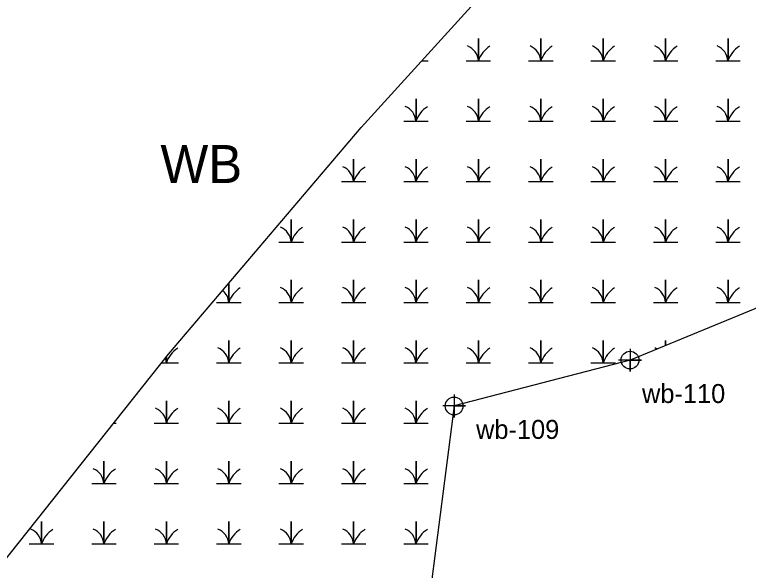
# Model space of a CAD drawing. Extents: x 2379288 to 2381905, y 330670 to 333511.
# Drawn here: x 2380290.9 to 2380484.3, y 332529.1 to 332675.5 of the extents above; entities that cross this region are included whole.
import ezdxf

# ---------------------------------------------------------------- set-up
doc = ezdxf.new("R2010")
doc.units = 0
for name, color, linetype in [('Default', 7, 'Continuous'), ('Exist Environmental Wetland Boundary', 7, 'Continuous'), ('Exist Environmental Wetland Boundary Cogo Number', 7, 'Continuous'), ('Exist Environmental Wetland Boundary Cogo Point CELL', 7, 'Continuous'), ('Exist Environmental Wetland Boundary Text', 7, 'Continuous'), ('Exist Hydro Swamp or Marsh', 7, 'Continuous')]:
    doc.layers.add(name, color=color, linetype=linetype)

msp = doc.modelspace()

# ---------------------------------------------------------------- linework, layer by layer
at = {"layer": 'Default'}
msp.add_lwpolyline([(2379288.07, 330873.37), (2380109.3, 332268.58), (2380147.86, 332331.82), (2380190.73, 332397.51), (2380235.65, 332461.81), (2380282.57, 332524.66), (2380331.46, 332586), (2380382.25, 332645.77), (2380434.91, 332703.9), (2380489.37, 332760.35), (2380545.59, 332815.05), (2380603.5, 332867.95), (2380663.06, 332918.99), (2380724.19, 332968.13), (2380786.85, 333015.32), (2380850.96, 333060.51), (2380916.47, 333103.65)], dxfattribs=at)
at = {"layer": 'Exist Environmental Wetland Boundary'}
msp.add_lwpolyline([(2380626.94, 332703.59), (2380578.61, 332658.53), (2380538.32, 332619.14), (2380494.95, 332601.64), (2380453.1, 332584.48), (2380406.72, 332572.38), (2380400.16, 332521.26), (2380412.11, 332496.92), (2380413.59, 332462.54), (2380386.06, 332425.71), (2380352.83, 332397.02), (2380315.67, 332385.64), (2380290.84, 332358.39), (2380295.85, 332340.3), (2380332.51, 332311.36), (2380326.97, 332300.58), (2380311.82, 332307.72), (2380244.82, 332322.56), (2380185.2, 332357.15), (2380173.71, 332371.44)], dxfattribs=at)
at = {"layer": 'Exist Environmental Wetland Boundary Cogo Point CELL'}
for points in [[(2380453.1, 332587.48), (2380453.1, 332581.48), (2380453.1, 332584.48), (2380456.1, 332584.48), (2380450.1, 332584.48)], [(2380406.72, 332575.38), (2380406.72, 332569.38), (2380406.72, 332572.38), (2380409.72, 332572.38), (2380403.72, 332572.38)]]:
    msp.add_lwpolyline(points, dxfattribs=at)
for centre in [(2380453.1, 332584.48), (2380406.72, 332572.38)]:
    msp.add_circle(centre, 2.34, dxfattribs=at)
at = {"layer": 'Exist Hydro Swamp or Marsh'}
for p, q in [((2380398.18, 332663.35), (2380399.9, 332663.35)), ((2380316.99, 332567.85), (2380317.65, 332567.85))]:
    msp.add_line(p, q, dxfattribs=at)
for points in [[(2380409.9, 332663.35), (2380413.13, 332663.35), (2380413.13, 332669.27), (2380413.13, 332663.35), (2380416.35, 332663.35)], [(2380426.35, 332663.35), (2380429.58, 332663.35), (2380429.58, 332669.27), (2380429.58, 332663.35), (2380432.81, 332663.35)], [(2380442.81, 332663.35), (2380446.03, 332663.35), (2380446.03, 332669.27), (2380446.03, 332663.35), (2380449.26, 332663.35)], [(2380459.26, 332663.35), (2380462.48, 332663.35), (2380462.48, 332669.27), (2380462.48, 332663.35), (2380465.71, 332663.35)], [(2380475.71, 332663.35), (2380478.93, 332663.35), (2380478.93, 332669.27), (2380478.93, 332663.35), (2380482.16, 332663.35)], [(2380393.45, 332647.43), (2380396.68, 332647.43), (2380396.68, 332653.35), (2380396.68, 332647.43), (2380399.9, 332647.43)], [(2380409.9, 332647.43), (2380413.13, 332647.43), (2380413.13, 332653.35), (2380413.13, 332647.43), (2380416.35, 332647.43)], [(2380426.35, 332647.43), (2380429.58, 332647.43), (2380429.58, 332653.35), (2380429.58, 332647.43), (2380432.81, 332647.43)], [(2380442.81, 332647.43), (2380446.03, 332647.43), (2380446.03, 332653.35), (2380446.03, 332647.43), (2380449.26, 332647.43)], [(2380459.26, 332647.43), (2380462.48, 332647.43), (2380462.48, 332653.35), (2380462.48, 332647.43), (2380465.71, 332647.43)], [(2380475.71, 332647.43), (2380478.93, 332647.43), (2380478.93, 332653.35), (2380478.93, 332647.43), (2380482.16, 332647.43)], [(2380377, 332631.52), (2380380.23, 332631.52), (2380380.23, 332637.43), (2380380.23, 332631.52), (2380383.45, 332631.52)], [(2380393.45, 332631.52), (2380396.68, 332631.52), (2380396.68, 332637.43), (2380396.68, 332631.52), (2380399.9, 332631.52)], [(2380409.9, 332631.52), (2380413.13, 332631.52), (2380413.13, 332637.43), (2380413.13, 332631.52), (2380416.35, 332631.52)], [(2380426.35, 332631.52), (2380429.58, 332631.52), (2380429.58, 332637.43), (2380429.58, 332631.52), (2380432.81, 332631.52)], [(2380442.81, 332631.52), (2380446.03, 332631.52), (2380446.03, 332637.43), (2380446.03, 332631.52), (2380449.26, 332631.52)], [(2380459.26, 332631.52), (2380462.48, 332631.52), (2380462.48, 332637.43), (2380462.48, 332631.52), (2380465.71, 332631.52)], [(2380475.71, 332631.52), (2380478.93, 332631.52), (2380478.93, 332637.43), (2380478.93, 332631.52), (2380482.16, 332631.52)], [(2380360.55, 332615.6), (2380363.78, 332615.6), (2380363.78, 332621.52), (2380363.78, 332615.6), (2380367, 332615.6)], [(2380377, 332615.6), (2380380.23, 332615.6), (2380380.23, 332621.52), (2380380.23, 332615.6), (2380383.45, 332615.6)], [(2380393.45, 332615.6), (2380396.68, 332615.6), (2380396.68, 332621.52), (2380396.68, 332615.6), (2380399.9, 332615.6)], [(2380409.9, 332615.6), (2380413.13, 332615.6), (2380413.13, 332621.52), (2380413.13, 332615.6), (2380416.35, 332615.6)], [(2380426.35, 332615.6), (2380429.58, 332615.6), (2380429.58, 332621.52), (2380429.58, 332615.6), (2380432.81, 332615.6)], [(2380442.81, 332615.6), (2380446.03, 332615.6), (2380446.03, 332621.52), (2380446.03, 332615.6), (2380449.26, 332615.6)], [(2380459.26, 332615.6), (2380462.48, 332615.6), (2380462.48, 332621.52), (2380462.48, 332615.6), (2380465.71, 332615.6)], [(2380475.71, 332615.6), (2380478.93, 332615.6), (2380478.93, 332621.52), (2380478.93, 332615.6), (2380482.16, 332615.6)], [(2380360.55, 332599.68), (2380363.78, 332599.68), (2380363.78, 332605.6), (2380363.78, 332599.68), (2380367, 332599.68)], [(2380377, 332599.68), (2380380.23, 332599.68), (2380380.23, 332605.6), (2380380.23, 332599.68), (2380383.45, 332599.68)], [(2380393.45, 332599.68), (2380396.68, 332599.68), (2380396.68, 332605.6), (2380396.68, 332599.68), (2380399.9, 332599.68)], [(2380409.9, 332599.68), (2380413.13, 332599.68), (2380413.13, 332605.6), (2380413.13, 332599.68), (2380416.35, 332599.68)], [(2380426.35, 332599.68), (2380429.58, 332599.68), (2380429.58, 332605.6), (2380429.58, 332599.68), (2380432.81, 332599.68)], [(2380442.81, 332599.68), (2380446.03, 332599.68), (2380446.03, 332605.6), (2380446.03, 332599.68), (2380449.26, 332599.68)], [(2380459.26, 332599.68), (2380462.48, 332599.68), (2380462.48, 332605.6), (2380462.48, 332599.68), (2380465.71, 332599.68)], [(2380475.71, 332599.68), (2380478.93, 332599.68), (2380478.93, 332605.6), (2380478.93, 332599.68), (2380482.16, 332599.68)], [(2380344.1, 332599.68), (2380347.32, 332599.68), (2380347.32, 332604.54)], [(2380347.32, 332604.54), (2380347.32, 332599.68), (2380350.55, 332599.68)], [(2380344.1, 332583.76), (2380347.32, 332583.76), (2380347.32, 332589.68), (2380347.32, 332583.76), (2380350.55, 332583.76)], [(2380360.55, 332583.76), (2380363.78, 332583.76), (2380363.78, 332589.68), (2380363.78, 332583.76), (2380367, 332583.76)], [(2380377, 332583.76), (2380380.23, 332583.76), (2380380.23, 332589.68), (2380380.23, 332583.76), (2380383.45, 332583.76)], [(2380393.45, 332583.76), (2380396.68, 332583.76), (2380396.68, 332589.68), (2380396.68, 332583.76), (2380399.9, 332583.76)], [(2380409.9, 332583.76), (2380413.13, 332583.76), (2380413.13, 332589.68), (2380413.13, 332583.76), (2380416.35, 332583.76)], [(2380426.35, 332583.76), (2380429.58, 332583.76), (2380429.58, 332589.68), (2380429.58, 332583.76), (2380432.81, 332583.76)], [(2380442.81, 332583.76), (2380446.03, 332583.76), (2380446.03, 332589.68), (2380446.03, 332583.76), (2380449.26, 332583.76)], [(2380462.48, 332588.33), (2380462.48, 332589.68), (2380462.48, 332588.33)], [(2380329.67, 332583.76), (2380330.87, 332583.76), (2380330.87, 332585.27)], [(2380330.87, 332585.27), (2380330.87, 332583.76), (2380334.1, 332583.76)], [(2380327.65, 332567.85), (2380330.87, 332567.85), (2380330.87, 332573.76), (2380330.87, 332567.85), (2380334.1, 332567.85)], [(2380344.1, 332567.85), (2380347.32, 332567.85), (2380347.32, 332573.76), (2380347.32, 332567.85), (2380350.55, 332567.85)], [(2380360.55, 332567.85), (2380363.78, 332567.85), (2380363.78, 332573.76), (2380363.78, 332567.85), (2380367, 332567.85)], [(2380377, 332567.85), (2380380.23, 332567.85), (2380380.23, 332573.76), (2380380.23, 332567.85), (2380383.45, 332567.85)], [(2380393.45, 332567.85), (2380396.68, 332567.85), (2380396.68, 332573.76), (2380396.68, 332567.85), (2380399.9, 332567.85)], [(2380311.2, 332551.93), (2380314.42, 332551.93), (2380314.42, 332557.85), (2380314.42, 332551.93), (2380317.65, 332551.93)], [(2380327.65, 332551.93), (2380330.87, 332551.93), (2380330.87, 332557.85), (2380330.87, 332551.93), (2380334.1, 332551.93)], [(2380344.1, 332551.93), (2380347.32, 332551.93), (2380347.32, 332557.85), (2380347.32, 332551.93), (2380350.55, 332551.93)], [(2380360.55, 332551.93), (2380363.78, 332551.93), (2380363.78, 332557.85), (2380363.78, 332551.93), (2380367, 332551.93)], [(2380377, 332551.93), (2380380.23, 332551.93), (2380380.23, 332557.85), (2380380.23, 332551.93), (2380383.45, 332551.93)], [(2380393.45, 332551.93), (2380396.68, 332551.93), (2380396.68, 332557.85), (2380396.68, 332551.93), (2380399.9, 332551.93)], [(2380294.74, 332536.01), (2380297.97, 332536.01), (2380297.97, 332541.93), (2380297.97, 332536.01), (2380301.2, 332536.01)], [(2380311.2, 332536.01), (2380314.42, 332536.01), (2380314.42, 332541.93), (2380314.42, 332536.01), (2380317.65, 332536.01)], [(2380327.65, 332536.01), (2380330.87, 332536.01), (2380330.87, 332541.93), (2380330.87, 332536.01), (2380334.1, 332536.01)], [(2380344.1, 332536.01), (2380347.32, 332536.01), (2380347.32, 332541.93), (2380347.32, 332536.01), (2380350.55, 332536.01)], [(2380360.55, 332536.01), (2380363.78, 332536.01), (2380363.78, 332541.93), (2380363.78, 332536.01), (2380367, 332536.01)], [(2380377, 332536.01), (2380380.23, 332536.01), (2380380.23, 332541.93), (2380380.23, 332536.01), (2380383.45, 332536.01)], [(2380393.45, 332536.01), (2380396.68, 332536.01), (2380396.68, 332541.93), (2380396.68, 332536.01), (2380399.9, 332536.01)]]:
    msp.add_lwpolyline(points, dxfattribs=at)
for centre, radius, start, end in [((2380408.53, 332663.02), 4.61, 4.1403, 67.535), ((2380419.97, 332661.08), 7.21, 122.1274, 161.6222), ((2380424.98, 332663.02), 4.61, 4.1403, 67.535), ((2380436.42, 332661.08), 7.21, 122.1274, 161.6222), ((2380441.43, 332663.02), 4.61, 4.1403, 67.535), ((2380452.87, 332661.08), 7.21, 122.1274, 161.6222), ((2380457.88, 332663.02), 4.61, 4.1403, 67.535), ((2380469.32, 332661.08), 7.21, 122.1274, 161.6222), ((2380474.33, 332663.02), 4.61, 4.1403, 67.535), ((2380485.77, 332661.08), 7.21, 122.1274, 161.6222), ((2380392.08, 332647.1), 4.61, 4.1403, 67.535), ((2380403.52, 332645.16), 7.21, 122.1274, 161.6222), ((2380408.53, 332647.1), 4.61, 4.1403, 67.535), ((2380419.97, 332645.16), 7.21, 122.1274, 161.6222), ((2380424.98, 332647.1), 4.61, 4.1403, 67.535), ((2380436.42, 332645.16), 7.21, 122.1274, 161.6222), ((2380441.43, 332647.1), 4.61, 4.1403, 67.535), ((2380452.87, 332645.16), 7.21, 122.1274, 161.6222), ((2380457.88, 332647.1), 4.61, 4.1403, 67.535), ((2380469.32, 332645.16), 7.21, 122.1274, 161.6222), ((2380474.33, 332647.1), 4.61, 4.1403, 67.535), ((2380485.77, 332645.16), 7.21, 122.1274, 161.6222), ((2380375.63, 332631.18), 4.61, 4.1403, 67.535), ((2380387.07, 332629.24), 7.21, 122.1274, 161.6222), ((2380392.08, 332631.18), 4.61, 4.1403, 67.535), ((2380403.52, 332629.24), 7.21, 122.1274, 161.6222), ((2380408.53, 332631.18), 4.61, 4.1403, 67.535), ((2380419.97, 332629.24), 7.21, 122.1274, 161.6222), ((2380424.98, 332631.18), 4.61, 4.1403, 67.535), ((2380436.42, 332629.24), 7.21, 122.1274, 161.6222), ((2380441.43, 332631.18), 4.61, 4.1403, 67.535), ((2380452.87, 332629.24), 7.21, 122.1274, 161.6222), ((2380457.88, 332631.18), 4.61, 4.1403, 67.535), ((2380469.32, 332629.24), 7.21, 122.1274, 161.6222), ((2380474.33, 332631.18), 4.61, 4.1403, 67.535), ((2380485.77, 332629.24), 7.21, 122.1274, 161.6222), ((2380359.18, 332615.27), 4.61, 4.1403, 67.535), ((2380370.62, 332613.33), 7.21, 122.1274, 161.6222), ((2380375.63, 332615.27), 4.61, 4.1403, 67.535), ((2380387.07, 332613.33), 7.21, 122.1274, 161.6222), ((2380392.08, 332615.27), 4.61, 4.1403, 67.535), ((2380403.52, 332613.33), 7.21, 122.1274, 161.6222), ((2380408.53, 332615.27), 4.61, 4.1403, 67.535), ((2380419.97, 332613.33), 7.21, 122.1274, 161.6222), ((2380424.98, 332615.27), 4.61, 4.1403, 67.535), ((2380436.42, 332613.33), 7.21, 122.1274, 161.6222), ((2380441.43, 332615.27), 4.61, 4.1403, 67.535), ((2380452.87, 332613.33), 7.21, 122.1274, 161.6222), ((2380457.88, 332615.27), 4.61, 4.1403, 67.535), ((2380469.32, 332613.33), 7.21, 122.1274, 161.6222), ((2380474.33, 332615.27), 4.61, 4.1403, 67.535), ((2380485.77, 332613.33), 7.21, 122.1274, 161.6222), ((2380354.16, 332597.41), 7.21, 122.1274, 161.6222), ((2380359.18, 332599.35), 4.61, 4.1403, 67.535), ((2380370.62, 332597.41), 7.21, 122.1274, 161.6222), ((2380375.63, 332599.35), 4.61, 4.1403, 67.535), ((2380387.07, 332597.41), 7.21, 122.1274, 161.6222), ((2380392.08, 332599.35), 4.61, 4.1403, 67.535), ((2380403.52, 332597.41), 7.21, 122.1274, 161.6222), ((2380408.53, 332599.35), 4.61, 4.1403, 67.535), ((2380419.97, 332597.41), 7.21, 122.1274, 161.6222), ((2380424.98, 332599.35), 4.61, 4.1403, 67.535), ((2380436.42, 332597.41), 7.21, 122.1274, 161.6222), ((2380441.43, 332599.35), 4.61, 4.1403, 67.535), ((2380452.87, 332597.41), 7.21, 122.1274, 161.6222), ((2380457.88, 332599.35), 4.61, 4.1403, 67.535), ((2380469.32, 332597.41), 7.21, 122.1274, 161.6222), ((2380474.33, 332599.35), 4.61, 4.1403, 67.535), ((2380485.77, 332597.41), 7.21, 122.1274, 161.6222), ((2380342.72, 332599.35), 4.61, 4.1403, 47.9334), ((2380337.71, 332581.49), 7.21, 122.1274, 161.6222), ((2380342.72, 332583.43), 4.61, 4.1403, 67.535), ((2380354.16, 332581.49), 7.21, 122.1274, 161.6222), ((2380359.18, 332583.43), 4.61, 4.1403, 67.535), ((2380370.62, 332581.49), 7.21, 122.1274, 161.6222), ((2380375.63, 332583.43), 4.61, 4.1403, 67.535), ((2380387.07, 332581.49), 7.21, 122.1274, 161.6222), ((2380392.08, 332583.43), 4.61, 4.1403, 67.535), ((2380403.52, 332581.49), 7.21, 122.1274, 161.6222), ((2380408.53, 332583.43), 4.61, 4.1403, 67.535), ((2380419.97, 332581.49), 7.21, 122.1274, 161.6222), ((2380424.98, 332583.43), 4.61, 4.1403, 67.535), ((2380436.42, 332581.49), 7.21, 122.1274, 161.6222), ((2380441.43, 332583.43), 4.61, 4.1403, 67.535), ((2380452.87, 332581.49), 7.21, 122.1274, 161.6222), ((2380457.88, 332583.43), 4.61, 59.5023, 67.535), ((2380326.27, 332583.43), 4.61, 4.1403, 19.3353), ((2380326.27, 332567.51), 4.61, 4.1403, 67.535), ((2380337.71, 332565.57), 7.21, 122.1274, 161.6222), ((2380342.72, 332567.51), 4.61, 4.1403, 67.535), ((2380354.16, 332565.57), 7.21, 122.1274, 161.6222), ((2380359.18, 332567.51), 4.61, 4.1403, 67.535), ((2380370.62, 332565.57), 7.21, 122.1274, 161.6222), ((2380375.63, 332567.51), 4.61, 4.1403, 67.535), ((2380387.07, 332565.57), 7.21, 122.1274, 161.6222), ((2380392.08, 332567.51), 4.61, 4.1403, 67.535), ((2380403.52, 332565.57), 7.21, 122.1274, 161.6222), ((2380309.82, 332551.59), 4.61, 4.1403, 67.535), ((2380321.26, 332549.66), 7.21, 122.1274, 161.6222), ((2380326.27, 332551.59), 4.61, 4.1403, 67.535), ((2380337.71, 332549.66), 7.21, 122.1274, 161.6222), ((2380342.72, 332551.59), 4.61, 4.1403, 67.535), ((2380354.16, 332549.66), 7.21, 122.1274, 161.6222), ((2380359.18, 332551.59), 4.61, 4.1403, 67.535), ((2380370.62, 332549.66), 7.21, 122.1274, 161.6222), ((2380375.63, 332551.59), 4.61, 4.1403, 67.535), ((2380387.07, 332549.66), 7.21, 122.1274, 161.6222), ((2380392.08, 332551.59), 4.61, 4.1403, 67.535), ((2380403.52, 332549.66), 7.21, 122.1274, 161.6222), ((2380293.37, 332535.68), 4.61, 4.1403, 67.535), ((2380304.81, 332533.74), 7.21, 122.1274, 161.6222), ((2380309.82, 332535.68), 4.61, 4.1403, 67.535), ((2380321.26, 332533.74), 7.21, 122.1274, 161.6222), ((2380326.27, 332535.68), 4.61, 4.1403, 67.535), ((2380337.71, 332533.74), 7.21, 122.1274, 161.6222), ((2380342.72, 332535.68), 4.61, 4.1403, 67.535), ((2380354.16, 332533.74), 7.21, 122.1274, 161.6222), ((2380359.18, 332535.68), 4.61, 4.1403, 67.535), ((2380370.62, 332533.74), 7.21, 122.1274, 161.6222), ((2380375.63, 332535.68), 4.61, 4.1403, 67.535), ((2380387.07, 332533.74), 7.21, 122.1274, 161.6222), ((2380392.08, 332535.68), 4.61, 4.1403, 67.535), ((2380403.52, 332533.74), 7.21, 122.1274, 161.6222)]:
    msp.add_arc(centre, radius, start, end, dxfattribs=at)

# ---------------------------------------------------------------- texts
at = {"layer": 'Exist Environmental Wetland Boundary Cogo Number'}
for s, p in [('wb-110', (2380456.27, 332573.16)), ('wb-109', (2380412.52, 332563.7))]:
    msp.add_text(s, height=5, dxfattribs=at).set_placement(p)
at = {"layer": 'Exist Environmental Wetland Boundary Text'}
msp.add_text('WB', height=10, dxfattribs=at).set_placement((2380329.31, 332631.16))

doc.saveas('drawing.dxf')
